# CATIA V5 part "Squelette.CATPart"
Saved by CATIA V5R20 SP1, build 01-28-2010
Part number: Squelette
Publications: "Plan.1", "Point.1", "Point.2"
Bounding box of the stored display mesh (mm): x 0 to 0, y 0 to 240, z 0 to 0
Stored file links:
  D:\Catia\IAO\A rendre\Squelette.CATPart
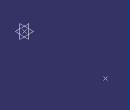
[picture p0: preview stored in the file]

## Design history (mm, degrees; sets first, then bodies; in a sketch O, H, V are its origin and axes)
Body1 (main body)
  Plane1 "Plan_Ref": type Offset, RefPlane yz-plane, Offset 0
  Point1 "Point A": (0, 0, 0)
  Point2 "Point D": (0, 240, 0)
